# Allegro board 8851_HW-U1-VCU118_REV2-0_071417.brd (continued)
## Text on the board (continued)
User.17: MGTAVCC | MGTAVTT | MGTVCCAUX | MH4 | C792 | R1325 | 1 | J19 | C54 | R854 | R857 | 24 | U111 | 7 | R823 | SW15 | 12 | C780 | C346 | 19 | J13 | SW14 | 2 | A1 | R1197 | U155 | C796 | R553 | R554 | R44 | C78 | U7 | C80 | R1021 | C222 | C221 | C220 | C207 | C16 | C225 | C224 | C223 | C209 | C208 | C210 | C211 | R152 | C190 | L66 | R1020 | C192 | J17 | R82 | J28 | R604 | 38 | R603 | 20 | C1327 | C1386 | C191 | R163 | C138 | R388 | R389 | C356 | C516 | C517 | C1576 | C1451 | C1577 | C1454 | R1073 | R1071 | C1756 | R379 | C919 | C1559 | C1518 | C1558 | C159 | C658 | R565 | R566 | C639 | C657 | C659 | C590 | C1574 | C1505 | C1474 | C1519 | R1072 | R1326 | C1557 | C602 | C596 | C519 | C520 | R1096 | C244 | C245 | L73 | U24 | C1235 | C1052 | C954 | C953 | C556 | C557 | R894 | C955 | R706 | R556 | R558 | C349 | R708 | R27 | R26 | R32 | R31 | R30 | 4 | 6 | 8 | C703 | C1138 | C558 | C696 | C1071 | C439 | C435 | R707 | R557 | R559 | C720 | C717 | C695 | C25 | C28 | R21 | C1581 | C1580 | C441 | C436 | 3 | 13 | 5 | 9 | L31 | C | E | G | J | L | N | MAC ID | 27 | C500 | C294 | 36 | R967 | R86 | R976 | R953 | 11 | F | D | H | K | M | A | B | C1232 | R952 | R957 | R972 | R956 | R968 | R974 | C1292 | R206 | R687 | C324 | C462 | R205 | C218 | C219 | C214 | C217 | C212 | C213 | C199 | R195 | R208 | R229 | R318 | R213 | R192 | C240 | 40 | C169 | U37 | J109 | C1754 | R1289 | R1290 | R601 | C158 | R113 | R114 | R1016 | C1304 | R1328 | C1753 | Z130 | C1604 | R582 | C1704 | C1681 | C1164 | C1466 | C1633 | R399 | C1475 | R352 | C1142 | C168 | C1600 | C1601 | C1407 | C1709 | C1208 | R901 | C1672 | C1671 | C1406 | 16 | U122 | C1694 | R1273 | R1255 | R563 | R1263 | R1236 | C1695 | R802 | J108 | C1675 | R1232 | C1676 | C1631 | C1673 | C1602 | C1597 | L97 | U165 | C1440 | C97 | R87 | J21 | C1701 | C1678 | C1591 | U162 | C134 | R62 | R63 | R64 | R34 | R39 | R65 | R68 | C86 | R101 | R102 | C128 | J38 | J54 | R460 | C1594 | C1702 | C1679 | R28 | R118 | R1288 | R1157 | C150 | DS3 | C1270 | R1145 | R955 | R964 | R971 | R966 | R963 | R959 | R970 | R958 | R960 | R424 | U160 | U161 | C231 | C1528 | C228 | C1665 | U159 | SW7 | U11 | C1364 | C1363 | C24 | C23 | C1666 | C358 | C1585 | C1705 | R499 | C1658 | C298 | C1657 | C1593 | C1592 | C1707 | C121 | C232 | C149 | C1590 | C1589 | C1706 | R131 | DS2 | C1664 | C1663 | C71 | C227 | C226 | R637 | C1661 | C1662 | R638 | POWER | 15 | C1712 | R1219 | R1216 | MH1 | USB UART | USB JTAG | ERR | SYS_1V0 | L63 | U111 BOOTMODE | M3 | M2 | M1 | M0 | TMS | TCK | TDO | TDI | L65 | S | SYS_1V8 | M40 | L40 | K40 | J40 | H40 | G40 | F40 | E40 | D40 | C40 | B40 | A40 | Z40 | Y40 | C1428 | Q18 | U151 | C1427 | T | R | USER_CLK_N | RLD3 Components | USER_CLK_P | C1739 | PCIE FINGER 16X | C1751 | CPU_RESET | C1733 | USER_CLOCK | L1 | K1 | J1 | H1 | G1 | F1 | E1 | D1 | C1 | B1 | Z1 | Y1 | C903 | VADJ INH | U | C165 | C1748 | R1204 | VCC1V8 | C1620 | DDR4_C2_VTT | C1617 | R1203 | C1743 | C1744 | U157 | L90 | C1616 | VCCINTIO_BRAM | DS1 | Q60 | VCC12 | VADJ_1V8 | DS26 | Q24 | Q37 | POR_OVERRIDE | PGOOD | GPIO LEDs | 0 | Q4 | INIT | GPIO | MOMENTARY | C151 | C195 | C1612 | C1606 | C1614 | C1607 | C1609 | C1610 | DONE | DS34 | +12V | VCC1V2 | R748 | DS42 | J16 | C872 | C795 | C243 | C241 | L60 | L61 | J110 | C144 | R855 | R856 | R29 | C143 | R84 | C129 | SW16 | C1316 | Z116 | Z115 | C1315 | Q39 | R202 | R197 | J11 | R162 | R166 | C1781 | C1632 | R58 | R355 | R1029 | C1273 | R1097 | C1342 | R1008 | C1358 | R23 | R24 | R596 | R597 | R177 | R178 | R1009 | R25 | R42 | R594 | R595 | R179 | R180 | C1247 | C60 | R569 | R251 | C61 | R567 | R249 | C107 | C350 | R250 | R247 | C698 | J99 | C718 | R299 | R259 | R1105 | C1073 | C437 | C723 | R257 | R564 | 10 | C52 | R258 | R246 | C353 | C555 | C560 | C697 | C706 | C56 | C700 | C106 | C108 | C491 | C1139 | C699 | C494 | R253 | R254 | C497 | C752 | C755 | R709 | C559 | R243 | R237 | R895 | C1488 | R239 | R252 | C440 | C719 | C721 | C434 | C1072 | C1487 | R241 | R238 | C1140 | C50 | C492 | C498 | C754 | C751 | C105 | R240 | R386 | R893 | R704 | R705 | C51 | R385 | C348 | C354 | R266 | R76 | C352 | C1053 | C702 | R1198 | C705 | R1007 | C496 | R255 | R245 | C749 | C756 | C1141 | C603 | C493 | R244 | R256 | C1054 | C704 | C707 | PIN | C716 | R242 | C1070 | R568 | C750 | C753 | 18 | C104 | C351 | R692 | R88 | R1177 | C722 | C604 | C30 | C495 | Z43 | C29 | R965 | R977 | C22 | R975 | C21 | R954 | C20 | C1549 | C19 | C1548 | C1479 | C589 | C619 | C1547 | C628 | C1520 | C33 | R700 | C1484 | C77 | C34 | C85 | C200 | C35 | C201 | R67 | C36 | C1483 | R61 | C1476 | C93 | C37 | C198 | C90 | R66 | C13 | R60 | C38 | C14 | C1755 | SW5 | C100 | C44 | R422 | R107 | C45 | MH2 | C46 | C101 | R435 | C47 | C1485 | C713 | C48 | C49 | J63 | C247 | R5 | C167 | C1506 | C1515 | R1083 | R1084 | R1085 | Z131 | R1087 | C95 | J100 | R172 | C94 | C1516 | U167 | C1303 | C1731 | R1015 | C53 | C1481 | C161 | C251 | R1171 | C1527 | R165 | C254 | C1158 | R926 | C248 | R1018 | R1017 | R803 | R900 | R799 | R792 | R801 | R1106 | R793 | L98 | C1181 | R804 | R112 | C1630 | C1669 | R1231 | C1670 | R111 | C1667 | C651 | C246 | R319 | C155 | C650 | R217 | D37 | C166 | R1140 | R1257 | C1698 | R1274 | C1599 | 1.8V | C1699 | C205 | R1264 | VADJ | R1237 | C89 | J107 | 1.2V | C622 | C88 | C177 | C1779 | C1398 | C180 | C1397 | C181 | C10 | R70 | C1680 | C176 | C9 | C1703 | C87 | R418 | R79 | C618 | R78 | C630 | D17 | D16 | D11 | C147 | R119 | R117 | R120 | D13 | R121 | R122 | D10 | R123 | R14 | R124 | C148 | R236 | D35 | C1588 | C1780 | C233 | C1778 | C527 | C1677 | C551 | C1700 | C910 | R139 | C1708 | C185 | C1595 | R1137 | C1596 | C1584 | C549 | R104 | C242 | C117 | R273 | R103 | R640 | R421 | C120 | R1235 | Q3 | SYSDONE | STAT | DS44 | SYSINIT | MGT226_CLK0_P | C789 | C790 | C791 | PCIe Test | SYSCON_POR | X2 | FM0 | FM1 | FM2 | SYS | EN | MGT226_CLK0_N | PHY1_RESET_B | 10/100/1000 ETHERNET | UTIL_1V35 | MGT233_CLK1_P | MGT233_CLK1_N | SYS_2V2 | B11 | GPIO DIP SW | B12 | C1348 | RLD3_C3_VTERM_0V6 | DDR4_C1_VTT | SYS_2V5 | C1426 | Q27 | C1736 | B82 | C1732 | C1419 | DS4 | DS5 | DS47 | DS36 | DS48 | DS46 | DS28 | DS27 | 3.3V | DS14 | SYSCLK | DS18 | DS13 | DS12 | DS10 | DS9 | DS8 | DS6 | DS7 | 12V FAN | DS21 | INT | DS49 | C1622 | DS24 | DS19 | DS16 | DS15 | VCCINT | DS17 | DS25 | UTIL_3V3 | Q17 | Q41 | Q36 | Q5 | Q6 | REG INH | MH6 | MH7 | R1324 | L35 | L34 | L93 | L94 | J82 | J18 | U115 | J31 | C68 | U34 | J3 | J78 | J36 | J30 | R730 | R729 | R728 | R727 | C905 | C1314 | U10 | J97 | J27 | J6 | SW12 | U19 | C438 | J9 | J35 | J7 | U142 | R97 | R8 | R786 | R96 | X5 | U57 | + | J34 | C460 | REV2.0 | HW-U1-VCU118 | U141 | SW4 | U38 | J22 | J105 | C911 | C956 | U39 | J14 | C171 | U25 | C957 | U53 | J2 | L89 | MH3 | D9 | R125 | U163 | L80 | U1 | R1136 | C206 | R1111 | Q42 | C1412 | J88 | U166 | C170 | J24 | C454 | D36 | C915 | C230 | Z15 | C1439 | J20 | C1438 | C174 | C215 | L88 | C1437 | Q9 | C216 | Q45 | J58 | J5 | R106 | L95 | R164 | J26 | C550 | C499 | Q19 | SW6 | C131 | R161 | R36 | SW17 | SW10 | Z94 | J23 | J12 | R1172 | J25 | C1431 | C1432 | U29 | J15 | SW9 | J52 | MH5 | L92 | SW1 | J101 | R169 | D33 | J53 | J4 | J106 | Q7 | U124 | J10 | QSFP+ | J96 | Q34 | Q35 | DS45 | P | Q | PROG | FMC HPC | U2 | C1740 | U40 | C1750 | FMC HPC1 | L91 | QSPI FLASH | U133 | U135 | U139 | U137 | U136 | C1618 | L76 | X6 | EMICAGE1 | BATT | C196 | C197 | R168 | C1757 | R1228 | C1758 | L79 | L77 | Q1 | DS20 | PMOD | J86 | C891 | C892 | C238 | C237 | R81 | D7 | J70 | Z88 | U145 | U123 | J33 | C156 | J32 | C896 | J104 | R300 | J65 | C58 | C59 | C895 | C825 | C18 | C17 | C32 | C31 | C42 | C43 | U32 | D38 | C461 | U80 | C92 | Z93 | Z86 | C1429 | C1430 | J73 | U36 | C257 | R231 | R95 | L3 | Q47 | Z7 | Z6 | C330 | C1445 | D19 | R1116 | J103 | J8 | C81 | C194 | L7 | C1413 | C146 | R1113 | Q43 | L74 | Z119 | R171 | J39 | C229 | C868 | C867 | L2 | L86 | L70 | L71 | L72 | DS43 | U104 | C1424 | DDR4 C2 COMPONENTS | C1623 | U138 | Q61 | L22 | L75 | U16 | R153 | L6 | C1421 | PMBus | VIEWED FROM TOP SIDE
User.18: 20 | L96 | C73 | BFRLPKVESCEM | 11 | R473 | R1244 | C1637 | R1222 | Z103 | Z104 | C145 | C188 | R136 | R141 | R137 | R74 | R159 | U6 | 8 | 4 | C130 | Z3 | Z2 | 6 | 7 | C1538 | U156 | Z65 | Z66 | C1715 | R1220 | Z96 | R756 | U30 | R1109 | R1130 | R1170 | C1411 | C1542 | R1169 | R223 | R221 | R220 | R222 | Z8 | Z120 | C1163 | R898 | R897 | R1233 | C1722 | C1638 | R1248 | R1259 | C1193 | C1146 | C1147 | C852 | C1543 | C1150 | C1144 | C1149 | C1143 | C1175 | C1152 | C849 | C1191 | C1219 | C1202 | R191 | C1224 | C1216 | C1160 | C1148 | C1211 | C250 | C249 | C1227 | C1145 | R377 | R384 | R150 | C1174 | R933 | C1178 | U9 | R1158 | C920 | C1523 | R921 | R1112 | R1159 | R1154 | C1395 | Z107 | Z108 | Z16 | Z14 | C1570 | C1464 | C1455 | C1452 | C1453 | C1450 | C1575 | C1571 | C1465 | C1462 | R175 | R383 | R378 | C334 | C1463 | C1569 | C1573 | C1568 | C1467 | C255 | C252 | C160 | R116 | R380 | R4 | C1305 | R1019 | C91 | R929 | R928 | 16 | 9 | Z128 | Z129 | C1186 | C1187 | R173 | BF | BD | BC | R581 | R160 | C1332 | BB | C132 | C522 | R1024 | BA | AW | AV | AU | C1572 | R1023 | AP | AN | AM | AL | C1331 | AJ | AD | AC | Y | W | V | U | T | R | P | N | M | L | K | J | H | G | F | 50 | C1282 | E | D | 54 | C | B | A | 1 | 45 | 15 | 10 | 40 | 35 | 30 | 25 | 5 | C1279 | C1759 | R988 | C1281 | C1240 | C1238 | C1237 | C1286 | C1285 | R1192 | R93 | R94 | R75 | R611 | R612 | R613 | R614 | R617 | R618 | C1551 | R356 | C1344 | R1095 | R1094 | R89 | R90 | R2 | R1 | R991 | U143 | R1052 | R1075 | R1076 | R1022 | C1325 | C1289 | C75 | R992 | R1074 | C1311 | U150 | R608 | R198 | R92 | R91 | R607 | R72 | R200 | R57 | R69 | R201 | R54 | R55 | R56 | C133 | R203 | R204 | R33 | C876 | C1336 | C1317 | C76 | R37 | C110 | C234 | C235 | C11 | C6 | C82 | C83 | C136 | C859 | R832 | R821 | C140 | C116 | C103 | C1579 | C142 | R724 | C913 | C774 | R776 | R773 | R774 | R772 | R808 | R816 | R815 | R819 | C803 | C798 | C801 | R1124 | C805 | C1343 | C822 | C811 | C834 | C841 | C835 | C810 | C879 | C830 | C808 | R135 | R133 | C806 | C837 | C842 | R810 | R811 | 2 | 3 | C1611 | Q10 | FPGA | Q26 | C1615 | U31 | D15 | Q28 | C1423 | C1486 | IIC EEPROM | A82 | A12 | A11 | A1 | R1225 | R478 | R468 | C1660 | R467 | R830 | C1587 | R1224 | R1230 | R1013 | R1223 | R132 | R1206 | R492 | R1201 | R945 | R484 | R1205 | R1253 | C1688 | R127 | C1586 | R1254 | C1691 | C1629 | R1265 | R598 | R483 | R1238 | C1659 | R482 | R472 | R1272 | R481 | C1690 | R486 | C1396 | R151 | R149 | C1719 | C1689 | R1241 | C1713 | R148 | R1261 | R1215 | R147 | R487 | R146 | R1183 | C1685 | R157 | R145 | R1269 | R488 | R158 | C1684 | R154 | R144 | R1268 | C184 | R143 | C1683 | C125 | R1267 | R156 | R920 | R925 | R909 | R907 | C1180 | C1159 | R919 | R903 | R917 | R896 | R904 | R905 | C1156 | C1215 | R918 | R902 | C1170 | C1157 | R916 | C1168 | R910 | C1546 | R911 | C1213 | R906 | R1199 | R913 | C1194 | C1526 | R908 | C1212 | C1668 | C1179 | R931 | R1147 | R922 | C1167 | C1598 | C1415 | R924 | C1169 | R1165 | C1155 | C1165 | R1280 | R912 | R15 | C1449 | R1164 | R899 | C1209 | R1213 | R923 | R18 | R17 | R333 | C1537 | C1188 | R1281 | R22 | R20 | R930 | R1256 | C1166 | R1229 | R1217 | R1239 | C1217 | R218 | C1173 | R193 | R1327 | C1171 | C1716 | C1218 | R1270 | R1131 | C1196 | C1720 | R1143 | R210 | R932 | R1132 | C1441 | C1172 | R1226 | R1125 | C331 | R1166 | C501 | C1408 | R219 | C1223 | C1724 | C1225 | R115 | C1176 | C1161 | C1182 | C853 | C1203 | C1197 | C1189 | C1204 | C851 | C1446 | C1531 | R939 | R937 | R935 | C1532 | R943 | C1153 | C1162 | R938 | R940 | R936 | R944 | C1177 | C1200 | C1192 | C1206 | R941 | C848 | R942 | C1198 | C1195 | C1228 | C1190 | C1221 | C850 | C1220 | C1226 | C1214 | C1210 | C1222 | C1207 | C1151 | R1293 | C1306 | C1154 | C1199 | R7 | Z98 | C253 | C1201 | C1539 | Z97 | R174 | C1205 | C1184 | C1185 | C923 | C1183 | R914 | R915 | R628 | U23 | R215 | R138 | R600 | Z101 | Z102 | BE | AY | C633 | AT | R185 | R181 | R182 | R186 | R108 | AR | R187 | R183 | R184 | R188 | AK | AF | AE | AB | AA | R1195 | R1193 | C1269 | C1293 | R1194 | C1233 | C1243 | R1292 | C1277 | C1291 | R990 | C1295 | C1236 | C1271 | C1392 | C1356 | C1359 | R683 | R1100 | R682 | R1090 | C126 | C239 | C62 | C63 | C1387 | C96 | R85 | R354 | U22 | C1330 | R59 | Z89 | R1079 | Z90 | C1313 | R1077 | R1078 | R824 | R1174 | R1070 | U125 | R71 | R1028 | C112 | C114 | C135 | C869 | C870 | C109 | U128 | C141 | R73 | R13 | 22 | 28 | R35 | R827 | C139 | R817 | C113 | C115 | C111 | C84 | R818 | C79 | C137 | R809 | C873 | C775 | R142 | R826 | R1196 | R775 | C820 | C1567 | C843 | R828 | C864 | C828 | R83 | R812 | C821 | C833 | C865 | C844 | R785 | C1608 | Q2 | Q16 | Q15 | Q14 | Q13 | Q12 | Q11 | Q22 | C914 | C1745 | C906 | C917 | C908 | C916 | Q59 | SD Card | U114 | U164 | C74 | C1634 | R1107 | R48 | C1443 | R500 | R327 | R502 | R501 | C1402 | C1544 | L83 | C871 | R839 | R334 | U41 | R838 | R47 | R316 | R837 | R46 | R49 | R134 | R1209 | U4 | R1208 | R1210 | R1318 | R167 | U51 | R1167 | R1108 | R1126 | R1144 | R1133 | R1319 | C1540 | C1409 | R1317 | U18 | L8 | R170 | R80 | R323 | R1135 | R110 | R109 | C1530 | RP2 | RP3 | C127 | U8 | R712 | C154 | Z118 | Z117 | U71 | C525 | R1139 | C258 | U35 | R1278 | C1108 | R892 | R890 | R128 | R129 | C740 | C423 | R515 | R199 | R155 | R362 | R214 | C157 | R1200 | C1674 | C1603 | R1207 | R1262 | R1214 | R1258 | R1266 | R1240 | C1442 | Z121 | C1718 | R1271 | C1721 | R1227 | R1279 | C1636 | R100 | R99 | U12 | D32 | R626 | R627 | R624 | R625 | R623 | R622 | R621 | R580 | R602 | U5 | Z132 | Z133 | R629 | R190 | R189 | R630 | C1649 | R331 | C640 | C858 | C1109 | R798 | R891 | R3 | C1012 | C1651 | R77 | C856 | C466 | R934 | R308 | R19 | C1244 | R1148 | Z92 | Z91 | R52 | R973 | R962 | R978 | R961 | R969 | R38 | R53 | C1298 | C204 | R951 | R105 | C27 | C1241 | C1239 | C26 | C1284 | C1283 | C1301 | C1288 | R1142 | U26 | R1190 | C518 | U3 | R43 | R51 | R50 | R40 | R41 | C1625 | C1643 | U33 | C69 | C66 | C122 | C1642 | C7 | R345 | L4 | C1641 | C289 | C467 | D8 | C102 | C118 | C119 | C67 | U44 | L67 | C12 | L5 | C1329 | C1328 | C1318 | C39 | C40 | R126 | U13 | R1101 | C543 | J83 | R498 | C1640 | C1583 | C470 | R574 | R573 | X7 | U131 | U154 | C878 | R813 | R805 | R814 | C57 | C295 | R575 | R860 | R784 | R787 | R726 | Q49 | C1613 | C193 | C1605 | Q21 | Q23 | U15 | Q58 | Q20 | Q8 | Q51 | Q25 | C918 | C1749 | C163 | C153 | C1624 | C1619 | QSPI FLASH | Q48 | U43 | C907 | C1752 | C164 | C1738 | C1737 | C902 | C1741 | C1734 | C1735 | U61 | U60 | U64 | U63 | U62 | C1354 | C1353 | Q40 | C3 | C1555 | C1556 | C1554 | C1350 | C1351 | C1352 | C1349 | U14 | Q54 | Q57 | C866 | C816 | C1714 | R820 | R324 | U42 | R639 | C72 | R1155 | R841 | C1524 | R1277 | R1276 | C1447 | R1114 | R196 | R1275 | C1534 | R1161 | R1160 | C1533 | C186 | C187 | R840 | C175 | C189 | R45 | D5 | C173 | D12 | D14 | D4 | L85 | C1404 | R321 | C124 | C152 | L48 | R480 | R434 | C480 | R479 | U27 | C98 | C406 | C370 | R1211 | R98 | C369 | R1247 | R464 | C729 | R463 | R888 | C1635 | R9 | C1725 | R1260 | R1252 | R1218 | C1639 | C1723 | R1221 | R1234 | C1717 | L82 | C1401 | R1127 | Z5 | Z4 | R1212 | U134 | R1251 | C1477 | C601 | U132 | C183 | C172 | R1088 | D39 | R547 | C162 | C1656 | R548 | C1011 | R130 | R560 | C1652 | C1550 | C1013 | R6 | C1650 | C1627 | C540 | C1655 | C615 | L13 | C1654 | C1578 | C623 | C1653 | L87 | C1628 | C614 | C236 | C2 | C922 | C15 | C4 | R1291 | C921 | C182 | R346 | C179 | R796 | C711 | C178 | C924 | C701 | C1517 | C1480 | C203 | C1245 | C202 | R194 | C1280 | C1294 | C1504 | C632 | R989 | C1478 | R176 | Z87 | C595 | C1246 | C1242 | C1290 | R1001 | R1002 | R1141 | C1300 | C1648 | C1287 | C1299 | C288 | R216 | C1296 | C290 | C1645 | C1272 | R861 | C1644 | C1391 | C41 | C1647 | C1390 | C893 | C1626 | C1388 | C894 | C1389 | C1646 | C451 | R1092 | C123 | U17 | C65 | U28 | C8 | R10 | C5 | C1 | C1345 | R12 | R11 | C1346 | C1552 | C1347 | C1553 | C874 | C99 | C862 | C70 | R16 | U109 | R211 | L62 | R212 | C794 | C64 | R1104 | X1 | R859 | R1103 | R858 | C1362 | R140 | C1582 | C55 | C1361 | C1566 | C1621 | C909 | C1742 | C1747 | C1746 | C1425 | DDR4 C1 COMPONENTS | C1420 | U20 | C788 | U21 | Q56 | Q55 | Q52 | Q53 | VIEWED FROM BOTTOM SIDE
User.19: BATT | MGTAVCC | MGTAVTT | MGTVCCAUX | 1 | 4 | J78 | USB JTAG | MH2 | MH6 | J5 | C796 | L60 | C880 | L93 | C346 | C54 | C881 | 24 | C1579 | D | 9 | 7 | 16 | L94 | 12 | R1324 | 19 | L61 | R1197 | R786 | 11 | J70 | SYS_1V8 | 51 | SYSINIT | 76 | C792 | R785 | DP2 | DP1 | STAT | SYSDONE | DP3 | 26 | J24 | U109 | C895 | R229 | L34 | R1325 | TDI | TDO | TCK | TMS | R585 | C644 | 2 | 38 | 20 | A | G | C | B | J | K | H | E | F | J73 | M1 | R344 | M2 | R266 | C26 | R603 | R604 | MAC ID | 40 | R856 | R857 | R855 | R854 | R792 | R793 | J38 | GPIO DIP SW | C1632 | R1151 | R1153 | USER CLK P | PCI-E FINGER 8X | R1150 | R1152 | U122 | R726 | SYSCLK | U146 | USER_CLOCK | C1260 | R998 | B1 | USER CLK N | C650 | J85 | C651 | D33 | R1140 | 104 | J84 | 53 | 3 | 5 | J23 | R121 | R122 | 6 | R1308 | R135 | R120 | R118 | R136 | R119 | R139 | R131 | C1570 | C1574 | C1550 | C924 | U147 | C1515 | C1505 | C1481 | C1504 | C1474 | C516 | U148 | DDR4_C1_VTT | J65 | R692 | C1572 | FMC HPC0 | SYS_2V5 | SYS_1V0 | J86 | C1483 | C14 | C13 | C1561 | C1560 | R418 | C1459 | C596 | C622 | C1406 | A1 | R953 | R967 | R1088 | C1484 | R339 | C659 | R990 | R1145 | R1148 | C1326 | C1460 | C1473 | C595 | D39 | U142 | 13 | C1590 | L | N | R1009 | C1273 | R1008 | C632 | C1247 | C1547 | C1559 | C1516 | C1557 | C1558 | C10 | C9 | C1475 | C602 | C1486 | C1592 | C1488 | BPI FLASH | J63 | C1633 | RLD3_C1_VTT | C1705 | FMC HPC1 | J80 | J81 | 8 | C1575 | C1571 | C1568 | M | C1293 | R954 | R975 | R977 | R965 | SW5 | R1235 | R976 | C1236 | C1294 | C1292 | CPU_RESET | C1487 | C1676 | R1232 | C1675 | C1760 | C1602 | C1673 | C1631 | C1585 | SW4 | C956 | C957 | J25 | PROG | C1445 | C1661 | VCCINT | C1589 | J107 | R1116 | C1604 | C1662 | C1706 | C1709 | C1593 | R756 | C1663 | C501 | C194 | J103 | C1584 | C502 | C1664 | U41 | C1707 | C1670 | R1231 | C1669 | UTIL_3V3 | R231 | UTIL_1V35 | C773 | C1597 | C1667 | C1630 | J97 | VADJ INH | C446 | J27 | C551 | C550 | C1405 | D13 | C614 | C1400 | C1399 | C1479 | C1519 | C1478 | D10 | DS3 | + | C1527 | C527 | FPGA | R1020 | VADJ | D35 | Z93 | Q39 | C1528 | PGOOD | R1021 | U49 | R352 | C1407 | C1429 | C1430 | R1137 | C1314 | Z94 | INT | C549 | C358 | R499 | SW7 | GPIO LEDs | C1432 | C1431 | C298 | C242 | R1171 | 0 | MOMENTARY | GPIO | R273 | R637 | REG INH | C235 | Q42 | Q43 | J100 | INIT | DS2 | R1172 | POWER | C537 | OFF | ON | DONE | R1194 | R1193 | R1195 | J77 | 12V | +12V | MH3 | 15 | C791 | C789 | J106 | U128 | 10 | R | Q34 | DS43 | DS44 | J4 | Q35 | J96 | X6 | U104 | T | C1423 | C1420 | C1416 | U151 | C1353 | L63 | U124 | C917 | C916 | C1738 | R1203 | R1204 | U160 | L98 | L79 | L91 | U161 | U162 | P3 | C1623 | C1616 | C1618 | C1615 | C1617 | C1620 | L97 | Q5 | C1428 | DS26 | Q4 | DS40 | DS34 | PCIe Test | U113 | C781 | C859 | POR_OVERRIDE | C1582 | J110 | C905 | HDMI | ERR | DS42 | C795 | U155 | C297 | 100 | C296 | USB UART | R319 | C509 | L35 | C896 | R579 | SYSTEM | M0 | 12V FAN | QSFP+ | DDR4_C2_VTT | J88 | C27 | M3 | R355 | R804 | R58 | EN | R802 | C779 | C161 | R799 | R803 | R952 | R801 | R957 | R1176 | C1272 | 52 | R972 | R687 | R956 | R968 | C159 | R974 | R563 | R1191 | C1391 | U112 | C1394 | C1393 | R818 | R809 | R115 | R597 | R819 | R948 | R596 | R815 | R947 | R594 | R816 | R595 | R808 | R996 | C873 | C1255 | C1256 | R849 | R995 | R949 | C1262 | R950 | R378 | C1261 | R1010 | R848 | R1000 | J74 | LN SIZE SEL | R1006 | R1067 | R1072 | C1454 | C460 | R1073 | C1458 | C919 | C1462 | R1071 | C1469 | C1453 | C1463 | C1464 | C921 | C357 | PIN | C1270 | R1007 | C156 | C160 | R989 | R1319 | CFP2 | C1657 | R955 | C1634 | R964 | C1658 | R971 | C1596 | C1595 | C1708 | R966 | C1778 | C1666 | C1665 | R963 | R959 | R970 | J109 | J108 | R958 | R960 | C1415 | C1599 | C1680 | C1704 | C1681 | C1703 | Z96 | C1440 | C1437 | C1629 | R1202 | C461 | C1438 | C1439 | C1601 | C1600 | C302 | C1672 | C1671 | C305 | C304 | C1700 | C1702 | R872 | C1677 | C1679 | C74 | C1588 | C257 | C454 | R873 | C1594 | R1318 | 10/100/1000 ETHERNET | C1779 | C303 | C1701 | R1257 | C1678 | C1698 | CP11 | C1591 | R1274 | R95 | R1317 | C504 | C771 | C1699 | C174 | C1780 | R1264 | R1255 | R1237 | D11 | C1694 | C240 | R1273 | R1029 | C1327 | 1.8V | C1695 | R1263 | C216 | C215 | R1236 | R460 | 1.2V | C1412 | 3.3V | C53 | R1136 | C1413 | C910 | C1315 | Z88 | R1111 | R399 | R550 | R1113 | C1316 | R640 | R421 | R638 | VCC1V8 | J54 | SYS_5V0 | J101 | VCC1V2 | PMBus | C788 | C790 | DS45 | Q18 | B11 | B12 | C1427 | U157 | C1417 | B49 | C1348 | C867 | C868 | C1425 | U159 | C1610 | C1424 | C1735 | C1758 | C1606 | C1757 | C1607 | C1611 | C1614 | C1612 | R1228 | L22 | DS31 | DS32 | DS33 | DS10 | DS9 | DS8 | DS49 | DS47 | DS6 | DS36 | DS7 | DS48 | DS24 | DS46 | DS28 | DS19 | DS16 | DS27 | Q36 | DS14 | DS15 | DS17 | DS25 | DS21 | C1421 | U34 | U115 | J3 | U145 | U19 | SW15 | J34 | J89 | J90 | J35 | L86 | C462 | J22 | C911 | L73 | J99 | Z | U1 | MH7 | REV 1.0 | HW-U1-VCU108 | U141 | J104 | L92 | J2 | L95 | L89 | L88 | SW16 | U58 | Q47 | MH4 | J14 | L3 | Q9 | C499 | R87 | U158 | SW6 | J58 | SW10 | L80 | SW17 | SW9 | J15 | J53 | SW1 | MH1 | J12 | J26 | J52 | U111 | P6 | U114 | U52 | J95 | P1 | U60 | U138 | U61 | U137 | U135 | U64 | U63 | U139 | U136 | U62 | U133 | U127 | C918 | U163 | L90 | U165 | Q41 | U166 | L75 | L76 | L77 | L66 | Q1 | L65 | L74 | L59 | J105 | MH5 | BULLSEYE GTY | D3 | J87 | D1 | SW14 | U32 | U144 | C915 | Q45 | J39 | L70 | L72 | L71 | SW12 | U16 | DDR4 C1 Components | Skt Torque 49in-lbs | DDR4 C2 Components | RLD3 Components | 47.5MM device | STANDARD
User.21: PCIe bracket
User.25: 1 OF 1
User.26: 1 OF 5
User.35: 3 | 1 | 2 | 4 | 5. J1 AND J96 ARE PRESSFIT CONNECTORS. | IPC-A-610, CLASS 2, CURRENT REVISION. | 2. BAG AND TAG (OR MARK CONTAINER) WITH PART NUMBER. | 3. REFERENCE SCHEMATIC (OR AVL) FOR BILL OF MATERIALS. | NOTES: (UNLESS OTHERWISE SPECIFIED) | 1. ASSEMBLE TO MEET INSPECTION CRITERIA OF | 4. ASSEMBLY SHOULD BE "ROHS" AND "LEAD FREE" COMPLIANT. | " FOLLOW THE XILINX SERIAL NUMBER CONVENTION.  FOR EXAMPLE KCU105 REV A IS NUMBERED | 9. DATASHEET SHOULD BE FOLLOWED FOR ALL HSMF-C155 DEVICES. | 8. SERIAL NUMBER INSTRUCTIONS:- | 10. DEFAULT JUMPER SETTINGS CAN BE FOUND IN THE PRODUCTION TEST INSTRUCTION DOCUMENT. | 11. ADD UNIQUE MAC ID STICKER BEFORE DELIVERY. | 1280723A001 TO 1280723A020, REV B SHOULD START AT 1280723B001 AND END AT 1280723B075" | FOR REV C IT SHOULD START AT 1280723C001 | 6. FAB IS BOUND TO USE "SAC305" SOLDER PASTE FOR COMPONENT ASSEMBLY. | 7(a) . VERIFY THAT THE SOLDER PASTE IS NOT APPLIED TO THE BGA PADS ON THE TOPSIDE. | (b). VERIFY THAT SOLDER PASTE IS NOT APPLIED TO THE UN-POPULATED RESISTORS AND CAPACITORS UNDERNEATH U1. | 5 | 1 OF 1 | ASSY,ROHS COMPLIANT | HW-U1-VCU118 | 0432092
User.37: 6.2 MIL | 11.5 MIL | 11 MIL | 36 | 5.5 MIL | 10.3 MIL | 9.5 MIL | 39 | 5.1 MIL | 9.35 MIL | 6.0 MIL | 43 | 50 | 42.5 | 3.5 MIL | 6.8 MIL | 7 MIL | 4.435 MIL | 5.5 MIL/6.5 MIL | 8.2 MIL/3.8 MIL | 7.4 MIL/4.6 MIL | 76 | 4.5 MIL/5.5 MIL | 7.2 MIL/4.8 MIL | 5.8 MIL/4.5 MIL | 6.4 MIL/4 MIL | 85 | 4.25 MIL/5.5 MIL | 7 MIL/5 MIL | 5.7 MIL/4.5 MIL | 86 | 4 MIL/5 MIL | 5.4 MIL/3.5 MIL | 5.2 MIL/4.8 MIL | 90 | 4.1 MIL/4.9 MIL | 3.5 MIL/7.5 MIL | 5.3 MIL/5.7 MIL | 4.5 MIL/4 MIL | 100 | 4.3 MIL/3.7 MIL | EDGE-COUPLED DIFFERENTIAL | 4.4 MIL/3.5 MIL | 4.2 MIL/3.8 MIL | 5 MIL/3.3 MIL | 4.3 MIL/3.5MIL | NECK MODE | 3.7 MIL/3.4 MIL | 3.0MIL/4.8 MIL | NECK MODE IN BACK DRILL AREA
User.45: NOTES: | - DRILL SIZES LISTED IN LEGEND ARE CONSIDERED FINISHED. | - PLEASE USE 17.7 MILS DRILL BIT TOOLING FOR 10 MILS FHS OVERDRILLING. | - PLEASE USE 19.7 MILS DRILL BIT TOOLING FOR 11 MILS FHS OVERDRILLING. | - LEGEND DOES NOT SPECIFY DEPTH INTO ADJACENT DIELECTRIC LAYER. | - 03_SIG1 IS MUST NOT CUT LAYER AND MAINTAIN STUB LENGTH OF 15 MILS OR BELOW. | - 05_SIG2 IS MUST NOT CUT LAYER AND MAINTAIN STUB LENGTH OF 15 MILS OR BELOW. | - 07_SIG3 IS MUST NOT CUT LAYER AND MAINTAIN STUB LENGTH OF 15 MILS OR BELOW. | - 10_GND IS MUST NOT CUT LAYER AND MAINTAIN STUB LENGTH OF 15 MILS OR BELOW. | FIGURE | FHS | 10.0 | 11.0 | TOLERANCE | +0.0/-10.0 | +0.0/-11.0 | BACKDRILL FROM BOTTOM | ALL UNITS ARE IN MILS | PLATED | QTY | 126 | 136 | 90 | 16 | 142 | 152 | 32 | ADDITIONAL | 8.0 | 12.0 | 30.0 | 32.0 | 36.0 | 40.0 | 41.0 | 47.0 | 48.0 | 62.0 | 63.0 | 71.0 | 73.0 | 106.0 | 125.0 | 34.0 | 35.0 | 50.0 | 52.0 | 61.0 | 87.0 | 119.0 | 127.0 | 33.0x26.0 | 60.0x32.0 | 45.0 | +0.0/-8.0 | +0.0/-12.0 | +2.0/-2.0 | +3.0/-3.0 | +2.0/-4.0 | +4.0/-2.0 | DRILL CHART: TOP to BOTTOM | DRILL CHART: TOP to 10_GND | NON-PLATED | 1519 | 7351 | 81 | 329 | 2 | 12 | 116 | 4 | 24 | 6 | 5 | 9 | 8 | 9534 | 113 | 115 | TOTAL HOLES: | 17. HARD GOLD ON FINGERS, 30-50 MICRO INCHES OF GOLD OVER 150-200 MICRO INCHES OF NICKLE MINIMUM. | 16. VIA IN PAD TECHNOLOGY USED: | VIA FILL IS REQUIRED: THIS IS A VIA IN PAD JOB. ALL VIA IN PAD LOCATIONS MUST BE COMPLETELY FILLED | WITH PETERS PP-2795 OR EQUIVALENT 100% SOLIDS FILL MATERIAL, PLANARIZED, AND PLATED OVER WITH | COPPER AND SURFACE FINISH. | 11. 100% ELECTRICAL TEST REQUIRED FOR CONTINUITY. BOARD SHALL HAVE A | 12. REMOVE ALL UNUSED PADS FROM INTERNAL LAYERS EXCEPT FROM L10. | 13. 274X GERBER/ODB++ USED FOR FAB MUST BE VERIFIED AGAINST THE PROVIDED IPC356 NETLIST. COPPER | 14. VIAS ARE SUPPOSED TO BE DIRECTLY CONNECTED TO RESPECTIVE PLANE. | 15. FOR IMPEDANCE CONTROL DETAILS REFER TO THE FILE "Whizz 8262.pdf" PROVIDED WITH GERBER DATA. | 10. VENDOR LOGO AND DATE CODE TO BE MARKED SOLDER  SIDE IN SILKSCREEN. MAXIMUM HEIGHT 0.12 INCHES. | 18. | 6. SOLDER MASK REQUIREMENTS FOR VIAS: | 3. MATERIAL: MEGTRON6 HVLP (RoHS COMPLIANT MATERIAL) OR EQUIVALENT. GLASS | 4. APPLY SOLDER MASK OVER BARE COPPER (SMOBC) IAW | 5. LPI SOLDER  MASK  TAIYO PSR4000 (RoHS COMPLIANT MATERIAL)  OR EQUIVALENT WILL BE  USED ON BOTH | 7. SOLDER MASK REGISTRATION TO BE WITHIN DIAMETRICAL TRUE POSITION OF + / - 0.002"WITH APPLICABLE | 8. FINISH: GOLD IMMERSION. | 9. SILKSCREEN USING WHITE - HAVEN PC421 ( NON-CONDUCTIVE  OR EQUIVALENT  RoHS COMPLIANT MATERIAL) | 2. BOARD SHALL MEET THE INSPECTION CRITERIA OF | 1. FABRICATE TO IPC-A-600, CURRENT REVISION | 1.GND SHORTED TO VCCINT_SNS_N, VADJ_1V8_FPGA_SNS_N, | NOTES: (UNLESS OTHERWISE SPECIFIED) | THIS FAB SHOULD BE "RoHS COMPLIANT". | b- QUALIFICATION AND PERFORMANCE AS PER IPC-6012 (LATEST REVISION)  CLASS II. | Intentional Short | IPC-SM-840, BOTH SIDES, USING LPI, COLOR GREEN. | TRANSITION TEMPERATURE MUST MEET OR EXCEED THE TEMPERATURE EXHIBITED | SIDES. | IN WRITING BY SUPPLIER. | WITH HIGH TEMPERATURE PROCESSES ASSOCIATED WITH LEAD FREE ASSEMBLY. | SLIVERS THAT ARE LESS THAN 0.003" IN WIDTH BETWEEN ANTI-PAD TO PLANE EDGE, ANTI-PAD TO SPLIT | HOLE / PAD. | FOR SLIVER REMOVAL ABOVE OR EQUAL TO THE 0.003" COPPER WIDTH MUST BE ADDRESSED AND APPROVED | PLANE AND ANTI-PAD TO ANTI-PAD MUST BE REMOVED FROM THE MANUFACTURING ARTWORK. A NETLIST | BOTH SIDES DISTORTION OF SILKSCREEN IS ACCEPTABLE  OVER TRACES.  EPOXY INK ON SOLDER LANDS IS | NOT ACCEPTABLE. | UL-RATING OF 94V-0. UL SYMBOL AND RATING SHALL BE MARKED SOLDER SIDE IN SILKSCREEN. | a- ACCEPTABILITY AS PER IPC-A-600 (LATEST REVISION) CLASS II | COMPARISON MUST BE PASSED WITH NO VIOLATION AFTER THE REMOVAL OF SLIVERS. ANY REQUIREMENT | a) VIA DRILLS TENTED(COVERED)FROM TOP SIDE AND ENCROACHED WITH SOLDER MASK RELIEF OF DRILL | b) PLUG TENTED VIA DRILLS FROM TOP SIDE ONLY AND FOLLOW GERBER FOR REST. | VCC1V8_FPGA_SNS_N, VCCINTIO_BRAM_FPGA_SNS_N, | UTIL_1V35_SNS_N, VCC1V2_FPGA_SNS_N, AGND10, AGND5, | AGND2, AGND1, AGND8, AGND13, AGND9, MGTAVCC_FPGA_SNS_N, | MGTAVTT_FPGA_SNS_N, AGND12, AGND6, UTIL_3V3_SNS_N, DXN | PLUS 6MIL FROM BOTTOM. | 15.VCC1V2 SHORTED TO 57N3732 | 16.61N7077 SHORTED TO 61N5776 | 17.56N1411 SHORTED TO 56N5656 | 18.55N3155 SHORTED TO 55N4756 | 19.77N4678 SHORTED TO 77N4651 | 25.57N3731 SHORTED TO 57N5412 | 9.VCC1V8 SHORTED TO 55N3156 | 8.61N7290 SHORTED TO 61N5743 | 3.VADJ_1V8 SHORTED TO 56N1434 | 4.77N2785  SHORTED TO 77N6252 | 26.5337N797 SHORTED TO 5337N2109 | 21.DDR4_C2_VTT SHORTED TO 64N2774 | 2.DDR4_C1_VTT SHORTED TO 64N651 | 23.VCCINT SHORTED TO VCCINT_VIN_R_P | 10.5337N798 SHORTED TO VCCINTIO_BRAM | 11.UTIL_3V3 SHORTED TO UTIL_3V3_SNS_P | 12.UTIL_1V35_SNS_P SHORTED TO UTIL_1V35 | 22.RLD3_C3_VTERM_0V6 SHORTED TO RLD3_SENSE | 14.VCC1V8_FPGA_SNS_P SHORTED TO VCC1V8_FPGA | 24.VCC1V2_FPGA_SNS_P SHORTED TO VCC1V2_FPGA | 5.MGTAVCC_FPGA_SNS_P SHORTED TO MGTAVCC_FPGA | 6.MGTAVTT_FPGA_SNS_P SHORTED TO MGTAVTT_FPGA | 13.VADJ_1V8_FPGA_SNS_P SHORTED TO VADJ_1V8_FPGA | 20.VCCINT_FPGA SHORTED TO VCCINT_VIN_R_N, VCCINT_SNS_P | 7.VCCINTIO_BRAM_FPGA_SNS_P SHORTED TO VCCINTIO_BRAM_FPGA | 5 OF 5 | 4 OF 5 | 2 OF 5 | 3 OF 5 | PCB,ROHS COMPLIANT | FABRICATION DRAWING | HW-U1-VCU117 | HW-U1-VCU118 | 1280906
